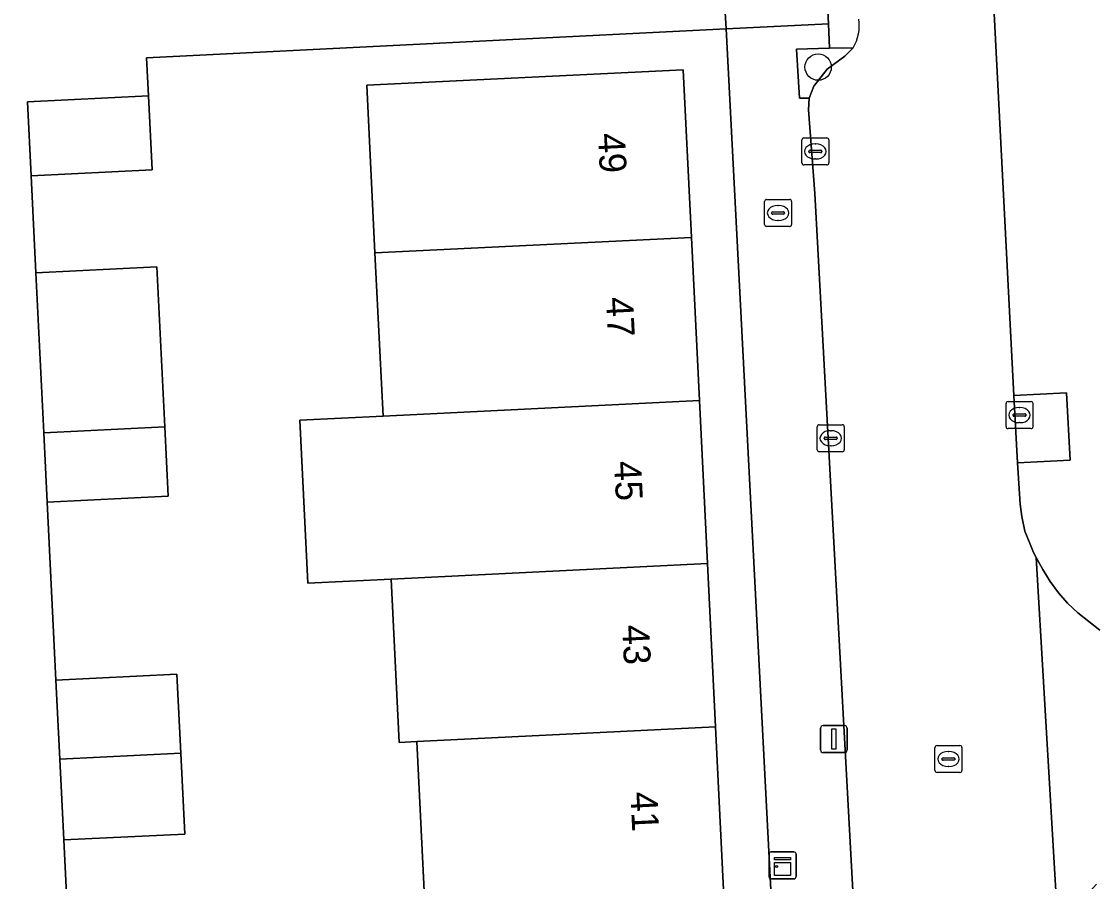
# Model space of a CAD drawing. Extents: x 161084 to 161928, y 385354 to 386522.
# Drawn here: x 161291.61 to 161331.43, y 386006.75 to 386038.67 of the extents above; entities that cross this region are included whole.
import ezdxf

# ---------------------------------------------------------------- set-up
doc = ezdxf.new("R2010")
doc.units = 0
for name, color, linetype in [('IMGEO_Boom', 7, 'Continuous'), ('IMGEO_Brandkraan', 7, 'Continuous'), ('IMGEO_Erf', 7, 'Continuous'), ('IMGEO_Groenvoorziening', 7, 'Continuous'), ('IMGEO_Kast', 7, 'Continuous'), ('IMGEO_Kolk', 7, 'Continuous'), ('IMGEO_Lichtmast', 7, 'Continuous'), ('IMGEO_Muur', 7, 'Continuous'), ('IMGEO_Pand', 7, 'Continuous'), ('IMGEO_Pand_nummerreeks', 7, 'Continuous'), ('IMGEO_Rijbaan_lokaal_open', 7, 'Continuous'), ('IMGEO_Rioolput', 7, 'Continuous'), ('IMGEO_Voetpad_open', 7, 'Continuous')]:
    doc.layers.add(name, color=color, linetype=linetype)

msp = doc.modelspace()

# ---------------------------------------------------------------- linework, layer by layer
at = {"layer": 'IMGEO_Boom'}
msp.add_circle((161321.177, 386036.972), 0.489, dxfattribs=at)
at = {"layer": 'IMGEO_Brandkraan'}
for p, q in [((161319.191, 386031.133), (161319.191, 386031.985)), ((161319.266, 386032.059), (161320.118, 386032.059)), ((161320.192, 386031.985), (161320.192, 386031.133)), ((161319.45, 386031.553), (161319.45, 386031.565)), ((161319.888, 386031.516), (161319.49, 386031.516)), ((161319.493, 386031.602), (161319.891, 386031.602)), ((161319.679, 386031.839), (161319.704, 386031.839)), ((161319.934, 386031.565), (161319.934, 386031.553)), ((161320.118, 386031.059), (161319.266, 386031.059)), ((161319.702, 386031.279), (161319.677, 386031.279))]:
    msp.add_line(p, q, dxfattribs=at)
for points in [[(161319.191, 386031.133), (161319.191, 386031.985)], [(161319.266, 386032.059), (161320.118, 386032.059)], [(161320.192, 386031.985), (161320.192, 386031.133)], [(161320.118, 386031.059), (161319.266, 386031.059)]]:
    msp.add_lwpolyline(points, dxfattribs=at)
for centre, radius, start, end in [((161319.268, 386031.983), 0.0765, 91.552, 178.448), ((161319.268, 386031.983), 0.0765, 91.552, 178.448), ((161320.116, 386031.983), 0.0765, 1.552, 88.448), ((161320.116, 386031.983), 0.0765, 1.552, 88.448), ((161319.49, 386031.562), 0.0403, 85.8775, 175.7526), ((161319.487, 386031.552), 0.0366, 178.938, 274.7102), ((161319.891, 386031.559), 0.043, 264.8664, 352.4533), ((161319.895, 386031.564), 0.0386, 1.7309, 96.639), ((161319.268, 386031.135), 0.0765, 181.552, 268.448), ((161319.268, 386031.135), 0.0765, 181.552, 268.448), ((161320.116, 386031.135), 0.0765, 271.552, 358.448), ((161320.116, 386031.135), 0.0765, 271.552, 358.448)]:
    msp.add_arc(centre, radius, start, end, dxfattribs=at)
for centre, major_axis, ratio, start_param, end_param in [((161319.678, 386031.559), (-0.387, 0.002), 0.722429, 4.712389, 7.853982), ((161319.703, 386031.559), (-0.39, 0.002), 0.717154, 1.570796, 4.712389)]:
    msp.add_ellipse(centre, major_axis=major_axis, ratio=ratio, start_param=start_param, end_param=end_param, dxfattribs=at)
at = {"layer": 'IMGEO_Erf'}
for points in [[(161319.752, 386000), (161317.767, 386038.387), (161296.252, 386037.322), (161296.322, 386035.904), (161296.457, 386033.155), (161291.971, 386032.933), (161292.148, 386029.339), (161296.634, 386029.561), (161296.926, 386023.623), (161297.053, 386021.051), (161292.567, 386020.829), (161292.892, 386014.224), (161297.378, 386014.446), (161297.522, 386011.517), (161297.67, 386008.514), (161293.184, 386008.292), (161293.482, 386002.243)], [(161306.579, 386005.896), (161306.282, 386011.948), (161305.625, 386011.916), (161305.327, 386017.969), (161302.241, 386017.817), (161301.943, 386023.87), (161305.029, 386024.022), (161304.731, 386030.074), (161304.425, 386036.296), (161316.171, 386036.874), (161316.478, 386030.652), (161316.775, 386024.6), (161317.073, 386018.547), (161317.371, 386012.494), (161317.669, 386006.442)]]:
    msp.add_lwpolyline(points, dxfattribs=at)
at = {"layer": 'IMGEO_Groenvoorziening'}
for points in [[(161322.164, 386037.38), (161322.479, 386037.689), (161321.604, 386037.669), (161320.379, 386037.642), (161320.488, 386035.816), (161320.842, 386035.815), (161321.017, 386036.261), (161321.512, 386036.894)], [(161330.392, 386024.88), (161328.441, 386024.784), (161328.569, 386022.29), (161330.527, 386022.387)]]:
    msp.add_lwpolyline(points, close=True, dxfattribs=at)
at = {"layer": 'IMGEO_Kast'}
for p, q in [((161319.357, 386006.923), (161319.357, 386007.764)), ((161319.357, 386007.764), (161319.357, 386006.923)), ((161319.432, 386007.848), (161320.273, 386007.848)), ((161320.273, 386007.848), (161319.432, 386007.848)), ((161320.357, 386007.773), (161320.357, 386006.932)), ((161320.357, 386006.932), (161320.357, 386007.773)), ((161320.282, 386006.848), (161319.441, 386006.848)), ((161319.441, 386006.848), (161320.282, 386006.848))]:
    msp.add_line(p, q, dxfattribs=at)
for points in [[(161319.552, 386007.638), (161320.152, 386007.638), (161320.152, 386007.553), (161319.552, 386007.553), (161319.552, 386007.638)], [(161319.552, 386007.463), (161320.152, 386007.463), (161320.152, 386006.974), (161319.552, 386006.974), (161319.552, 386007.463)]]:
    msp.add_lwpolyline(points, dxfattribs=at)
msp.add_circle((161319.636, 386007.312), 0.0377, dxfattribs=at)
for centre, start, end in [((161319.435, 386007.77), 92.4484, 184.2845), ((161319.435, 386007.77), 92.4484, 184.2845), ((161320.279, 386007.77), 2.4484, 94.2845), ((161320.279, 386007.77), 2.4484, 94.2845), ((161319.435, 386006.926), 182.4484, 274.2845), ((161319.435, 386006.926), 182.4484, 274.2845), ((161320.279, 386006.926), 272.4484, 4.2845), ((161320.279, 386006.926), 272.4484, 4.2845)]:
    msp.add_arc(centre, 0.0779, start, end, dxfattribs=at)
at = {"layer": 'IMGEO_Kolk'}
for p, q in [((161320.573, 386033.416), (161320.573, 386034.268)), ((161320.648, 386034.342), (161321.5, 386034.342)), ((161321.574, 386034.268), (161321.574, 386033.416)), ((161320.832, 386033.836), (161320.832, 386033.848)), ((161320.875, 386033.885), (161321.273, 386033.885)), ((161321.061, 386034.122), (161321.086, 386034.122)), ((161321.316, 386033.848), (161321.316, 386033.836)), ((161321.27, 386033.799), (161320.872, 386033.799)), ((161321.084, 386033.562), (161321.059, 386033.562)), ((161321.5, 386033.342), (161320.648, 386033.342)), ((161328.149, 386023.632), (161328.149, 386024.484)), ((161328.224, 386024.558), (161329.076, 386024.558)), ((161328.637, 386024.338), (161328.662, 386024.338)), ((161329.15, 386024.484), (161329.15, 386023.632)), ((161328.408, 386024.052), (161328.408, 386024.064)), ((161328.846, 386024.015), (161328.448, 386024.015)), ((161328.451, 386024.101), (161328.849, 386024.101)), ((161328.892, 386024.064), (161328.892, 386024.052)), ((161321.145, 386022.775), (161321.145, 386023.627)), ((161321.22, 386023.701), (161322.072, 386023.701)), ((161322.146, 386023.627), (161322.146, 386022.775)), ((161329.076, 386023.558), (161328.224, 386023.558)), ((161328.66, 386023.778), (161328.635, 386023.778)), ((161321.404, 386023.195), (161321.404, 386023.207)), ((161321.842, 386023.158), (161321.444, 386023.158)), ((161321.447, 386023.244), (161321.845, 386023.244)), ((161321.633, 386023.481), (161321.658, 386023.481)), ((161321.888, 386023.207), (161321.888, 386023.195)), ((161322.072, 386022.701), (161321.22, 386022.701)), ((161321.656, 386022.921), (161321.631, 386022.921))]:
    msp.add_line(p, q, dxfattribs=at)
for points in [[(161320.573, 386033.416), (161320.573, 386034.268)], [(161320.648, 386034.342), (161321.5, 386034.342)], [(161321.574, 386034.268), (161321.574, 386033.416)], [(161321.5, 386033.342), (161320.648, 386033.342)], [(161328.149, 386023.632), (161328.149, 386024.484)], [(161328.224, 386024.558), (161329.076, 386024.558)], [(161329.15, 386024.484), (161329.15, 386023.632)], [(161321.145, 386022.775), (161321.145, 386023.627)], [(161321.22, 386023.701), (161322.072, 386023.701)], [(161322.146, 386023.627), (161322.146, 386022.775)], [(161329.076, 386023.558), (161328.224, 386023.558)], [(161322.072, 386022.701), (161321.22, 386022.701)]]:
    msp.add_lwpolyline(points, dxfattribs=at)
for centre, radius, start, end in [((161320.65, 386034.266), 0.0765, 91.552, 178.448), ((161320.65, 386034.266), 0.0765, 91.552, 178.448), ((161321.498, 386034.266), 0.0765, 1.552, 88.448), ((161321.498, 386034.266), 0.0765, 1.552, 88.448), ((161320.872, 386033.845), 0.0403, 85.8775, 175.7526), ((161321.277, 386033.847), 0.0386, 1.7309, 96.639), ((161320.869, 386033.835), 0.0366, 178.938, 274.7102), ((161321.273, 386033.842), 0.043, 264.8664, 352.4533), ((161320.65, 386033.418), 0.0765, 181.552, 268.448), ((161320.65, 386033.418), 0.0765, 181.552, 268.448), ((161321.498, 386033.418), 0.0765, 271.552, 358.448), ((161321.498, 386033.418), 0.0765, 271.552, 358.448), ((161328.226, 386024.482), 0.0765, 91.552, 178.448), ((161328.226, 386024.482), 0.0765, 91.552, 178.448), ((161329.074, 386024.482), 0.0765, 1.552, 88.448), ((161329.074, 386024.482), 0.0765, 1.552, 88.448), ((161328.448, 386024.061), 0.0403, 85.8775, 175.7526), ((161328.445, 386024.051), 0.0366, 178.938, 274.7102), ((161328.849, 386024.058), 0.043, 264.8664, 352.4533), ((161328.853, 386024.063), 0.0386, 1.7309, 96.639), ((161321.222, 386023.625), 0.0765, 91.552, 178.448), ((161321.222, 386023.625), 0.0765, 91.552, 178.448), ((161322.07, 386023.625), 0.0765, 1.552, 88.448), ((161322.07, 386023.625), 0.0765, 1.552, 88.448), ((161328.226, 386023.634), 0.0765, 181.552, 268.448), ((161328.226, 386023.634), 0.0765, 181.552, 268.448), ((161329.074, 386023.634), 0.0765, 271.552, 358.448), ((161329.074, 386023.634), 0.0765, 271.552, 358.448), ((161321.444, 386023.204), 0.0403, 85.8775, 175.7526), ((161321.441, 386023.194), 0.0366, 178.938, 274.7102), ((161321.845, 386023.201), 0.043, 264.8664, 352.4533), ((161321.849, 386023.206), 0.0386, 1.7309, 96.639), ((161321.222, 386022.777), 0.0765, 181.552, 268.448), ((161321.222, 386022.777), 0.0765, 181.552, 268.448), ((161322.07, 386022.777), 0.0765, 271.552, 358.448), ((161322.07, 386022.777), 0.0765, 271.552, 358.448)]:
    msp.add_arc(centre, radius, start, end, dxfattribs=at)
for centre, major_axis, ratio, start_param, end_param in [((161321.06, 386033.842), (-0.387, 0.002), 0.722429, 4.712389, 7.853982), ((161321.085, 386033.842), (-0.39, 0.002), 0.717154, 1.570796, 4.712389), ((161328.636, 386024.058), (-0.387, 0.002), 0.722429, 4.712389, 7.853982), ((161328.661, 386024.058), (-0.39, 0.002), 0.717154, 1.570796, 4.712389), ((161321.632, 386023.201), (-0.387, 0.002), 0.722429, 4.712389, 7.853982), ((161321.657, 386023.201), (-0.39, 0.002), 0.717154, 1.570796, 4.712389)]:
    msp.add_ellipse(centre, major_axis=major_axis, ratio=ratio, start_param=start_param, end_param=end_param, dxfattribs=at)
at = {"layer": 'IMGEO_Lichtmast'}
for p, q in [((161321.265, 386011.636), (161321.265, 386012.436)), ((161321.265, 386012.436), (161321.265, 386011.636)), ((161321.365, 386012.536), (161322.155, 386012.536)), ((161322.155, 386012.536), (161321.365, 386012.536)), ((161322.255, 386012.436), (161322.255, 386011.636)), ((161322.255, 386011.636), (161322.255, 386012.436)), ((161322.155, 386011.536), (161321.365, 386011.536)), ((161321.365, 386011.536), (161322.155, 386011.536))]:
    msp.add_line(p, q, dxfattribs=at)
msp.add_lwpolyline([(161321.685, 386012.411), (161321.835, 386012.411), (161321.835, 386011.661), (161321.685, 386011.661), (161321.685, 386012.411)], dxfattribs=at)
for centre, start, end in [((161321.365, 386012.436), 90, 180), ((161321.365, 386012.436), 90, 180), ((161322.155, 386012.436), 0, 90), ((161322.155, 386012.436), 360, 90), ((161321.365, 386011.636), 180, 270), ((161321.365, 386011.636), 180, 270), ((161322.155, 386011.636), 270, 0), ((161322.155, 386011.636), 270, 0)]:
    msp.add_arc(centre, 0.1, start, end, dxfattribs=at)
at = {"layer": 'IMGEO_Muur'}
for points in [[(161292.148, 386029.339), (161291.971, 386032.933)], [(161292.892, 386014.224), (161292.567, 386020.829)], [(161293.482, 386002.243), (161293.184, 386008.292)]]:
    msp.add_lwpolyline(points, dxfattribs=at)
at = {"layer": 'IMGEO_Pand'}
for points in [[(161316.171, 386036.874), (161304.425, 386036.296), (161304.731, 386030.074), (161316.478, 386030.652)], [(161291.836, 386035.681), (161291.971, 386032.933), (161296.457, 386033.155), (161296.322, 386035.904)], [(161316.478, 386030.652), (161304.731, 386030.074), (161305.029, 386024.022), (161316.775, 386024.6)], [(161292.44, 386023.403), (161296.926, 386023.623), (161296.634, 386029.561), (161292.148, 386029.339)], [(161316.775, 386024.6), (161305.029, 386024.022), (161301.943, 386023.87), (161302.241, 386017.817), (161305.327, 386017.969), (161317.073, 386018.547)], [(161292.567, 386020.829), (161297.053, 386021.051), (161296.926, 386023.623), (161292.44, 386023.403)], [(161317.371, 386012.494), (161317.073, 386018.547), (161305.327, 386017.969), (161305.625, 386011.916), (161306.282, 386011.948)], [(161293.036, 386011.296), (161297.522, 386011.517), (161297.378, 386014.446), (161292.892, 386014.224)], [(161317.669, 386006.442), (161317.371, 386012.494), (161306.282, 386011.948), (161306.579, 386005.896), (161309.039, 386006.017)], [(161293.184, 386008.292), (161297.67, 386008.514), (161297.522, 386011.517), (161293.036, 386011.296)]]:
    msp.add_lwpolyline(points, close=True, dxfattribs=at)
at = {"layer": 'IMGEO_Rijbaan_lokaal_open'}
for points in [[(161287.514, 385985.354), (161294.301, 385985.614), (161294.228, 385987.083), (161294.105, 385989.575), (161293.903, 385993.65), (161293.755, 385996.678), (161293.632, 385999.193), (161293.592, 386000), (161293.482, 386002.243), (161293.184, 386008.292), (161293.036, 386011.296), (161292.892, 386014.224), (161292.567, 386020.829), (161292.44, 386023.403), (161292.148, 386029.339), (161291.971, 386032.933), (161291.836, 386035.681), (161296.322, 386035.904), (161296.252, 386037.322), (161317.767, 386038.387), (161317.411, 386044.073)], [(161331.473, 385970.92), (161331.366, 385973.031), (161331.304, 385974.243), (161329.994, 386000), (161329.881, 386000.815), (161329.869, 386002.437), (161329.876, 386002.954), (161329.928, 386003.467), (161330.026, 386003.974), (161330.12, 386004.301), (161329.27, 386018.77), (161329.175, 386018.961), (161329.044, 386019.267), (161328.849, 386019.758), (161328.736, 386020.294), (161328.677, 386020.748), (161328.569, 386022.29), (161328.441, 386024.784), (161327.688, 386039.443)], [(161322.479, 386037.689), (161322.164, 386037.38), (161321.512, 386036.894), (161321.017, 386036.261), (161320.842, 386035.815), (161320.82, 386035.383), (161321.051, 386032.281), (161322.806, 386000.044), (161323.551, 385986.175), (161323.863, 385979.38), (161324.123, 385974.12), (161324.303, 385970.882), (161324.405, 385967.984), (161324.739, 385961.72), (161325.01, 385956.233), (161325.394, 385949.374), (161326.147, 385934.319), (161333.016, 385934.637)], [(161331.634, 386016.08), (161331.218, 386016.4), (161330.812, 386016.721), (161330.435, 386017.077), (161330.093, 386017.466), (161329.786, 386017.883), (161329.518, 386018.326), (161329.27, 386018.77), (161330.12, 386004.301), (161330.169, 386004.47), (161330.356, 386004.951), (161330.585, 386005.413), (161330.854, 386005.854), (161331.162, 386006.268), (161331.505, 386006.653)]]:
    msp.add_lwpolyline(points, dxfattribs=at)
msp.add_arc((161321.042, 386038.527), 1.664, 329.7423, 7.6171, dxfattribs=at)
at = {"layer": 'IMGEO_Rioolput'}
for p, q in [((161325.513, 386010.872), (161325.513, 386011.724)), ((161325.588, 386011.798), (161326.44, 386011.798)), ((161326.001, 386011.578), (161326.026, 386011.578)), ((161326.514, 386011.724), (161326.514, 386010.872)), ((161325.772, 386011.292), (161325.772, 386011.304)), ((161326.21, 386011.255), (161325.812, 386011.255)), ((161325.815, 386011.341), (161326.213, 386011.341)), ((161326.256, 386011.304), (161326.256, 386011.292)), ((161326.44, 386010.798), (161325.588, 386010.798)), ((161326.024, 386011.018), (161325.999, 386011.018))]:
    msp.add_line(p, q, dxfattribs=at)
for points in [[(161325.513, 386010.872), (161325.513, 386011.724)], [(161325.588, 386011.798), (161326.44, 386011.798)], [(161326.514, 386011.724), (161326.514, 386010.872)], [(161326.44, 386010.798), (161325.588, 386010.798)]]:
    msp.add_lwpolyline(points, dxfattribs=at)
for centre, radius, start, end in [((161325.59, 386011.722), 0.0765, 91.552, 178.448), ((161325.59, 386011.722), 0.0765, 91.552, 178.448), ((161326.438, 386011.722), 0.0765, 1.552, 88.448), ((161326.438, 386011.722), 0.0765, 1.552, 88.448), ((161325.812, 386011.301), 0.0403, 85.8775, 175.7526), ((161325.809, 386011.291), 0.0366, 178.938, 274.7102), ((161326.213, 386011.298), 0.043, 264.8664, 352.4533), ((161326.217, 386011.303), 0.0386, 1.7309, 96.639), ((161325.59, 386010.874), 0.0765, 181.552, 268.448), ((161325.59, 386010.874), 0.0765, 181.552, 268.448), ((161326.438, 386010.874), 0.0765, 271.552, 358.448), ((161326.438, 386010.874), 0.0765, 271.552, 358.448)]:
    msp.add_arc(centre, radius, start, end, dxfattribs=at)
for centre, major_axis, ratio, start_param, end_param in [((161326, 386011.298), (-0.387, 0.002), 0.722429, 4.712389, 7.853982), ((161326.025, 386011.298), (-0.39, 0.002), 0.717154, 1.570796, 4.712389)]:
    msp.add_ellipse(centre, major_axis=major_axis, ratio=ratio, start_param=start_param, end_param=end_param, dxfattribs=at)
at = {"layer": 'IMGEO_Voetpad_open'}
msp.add_lwpolyline([(161321.23, 386044.898), (161317.411, 386044.073), (161317.767, 386038.387), (161321.557, 386038.583)], close=True, dxfattribs=at)
for points in [[(161322.406, 386044.972), (161321.23, 386044.898), (161321.557, 386038.583), (161321.604, 386037.669), (161322.479, 386037.689)], [(161327.688, 386039.443), (161328.441, 386024.784), (161330.392, 386024.88), (161330.527, 386022.387), (161328.569, 386022.29), (161328.677, 386020.748), (161328.736, 386020.294), (161328.849, 386019.758), (161329.044, 386019.267), (161329.175, 386018.961), (161329.27, 386018.77), (161329.518, 386018.326), (161329.786, 386017.883), (161330.093, 386017.466), (161330.435, 386017.077), (161330.812, 386016.721), (161331.218, 386016.4), (161331.634, 386016.08)], [(161324.405, 385967.984), (161324.303, 385970.882), (161324.123, 385974.12), (161323.863, 385979.38), (161323.551, 385986.175), (161322.806, 386000.044), (161321.051, 386032.281), (161320.82, 386035.383), (161320.842, 386035.815), (161320.488, 386035.816), (161320.379, 386037.642), (161321.604, 386037.669), (161321.557, 386038.583), (161317.767, 386038.387), (161319.752, 386000), (161320.598, 385985.282), (161320.942, 385979.292), (161321.127, 385976.067), (161321.21, 385974.381), (161321.246, 385973.665), (161321.39, 385970.769), (161321.564, 385967.293)]]:
    msp.add_lwpolyline(points, dxfattribs=at)
msp.add_arc((161321.042, 386038.527), 1.664, 329.7423, 7.6171, dxfattribs=at)

# ---------------------------------------------------------------- texts
at = {"layer": 'IMGEO_Pand_nummerreeks'}
for s, rotation, p in [('49', 272.8187, (161313.004, 386034.504)), ('47', 272.8187, (161313.303, 386028.422)), ('45', 272.8187, (161313.603, 386022.34)), ('43', 272.8175, (161313.902, 386016.258)), ('41', 272.8175, (161314.207, 386010.064))]:
    msp.add_text(s, height=1, rotation=rotation, dxfattribs=at).set_placement(p)

doc.saveas('drawing.dxf')
